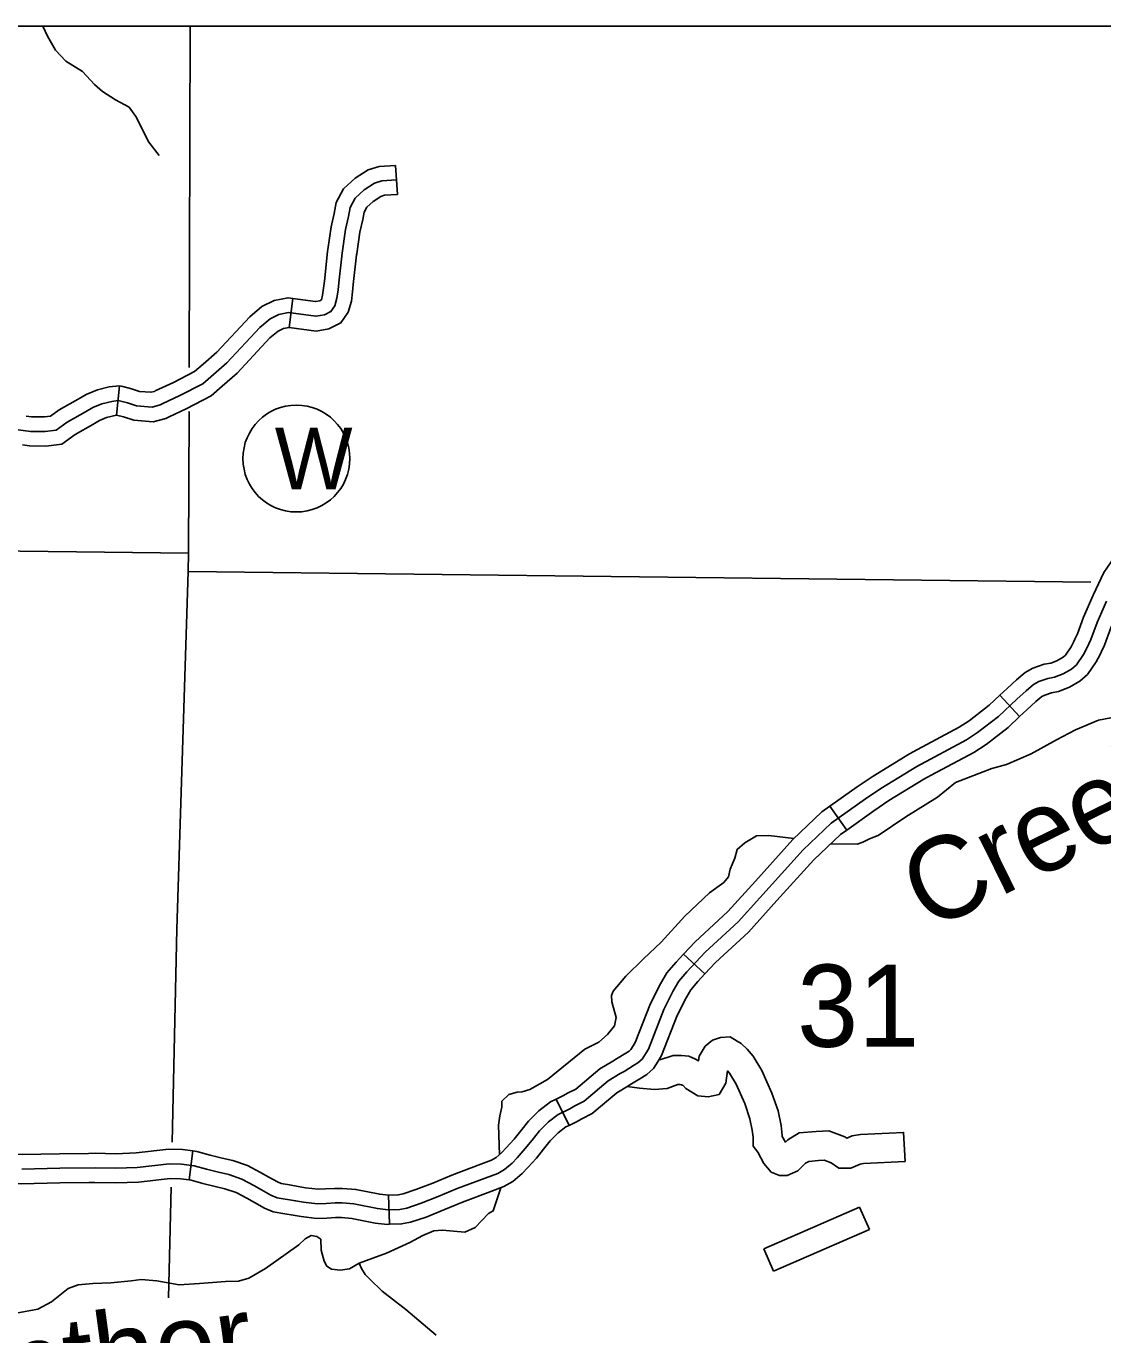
# Model space of a CAD drawing. Extents: x 0 to 3171, y 0 to 2059.
# Drawn here: x 1400.7 to 1493, y 1142.5 to 1254.6 of the extents above; entities that cross this region are included whole.
import ezdxf

# ---------------------------------------------------------------- set-up
doc = ezdxf.new("R2010")
doc.units = 0
for name, color, linetype in [('Default', 7, 'Continuous'), ('Level 35', 7, 'Continuous'), ('Level 4', 7, 'Continuous'), ('Level 45', 7, 'Continuous'), ('Level 46', 7, 'Continuous'), ('Level 5', 7, 'Continuous'), ('Level 57', 7, 'Continuous')]:
    doc.layers.add(name, color=color, linetype=linetype)

msp = doc.modelspace()

# ---------------------------------------------------------------- linework, layer by layer
at = {"layer": 'Default'}
msp.add_line((2119.81, 1254.61), (1029.42, 1254.61), dxfattribs=at)
msp.add_lwpolyline([(2119.81, 1254.61), (1029.42, 1254.61), (1029.42, 254.41), (2119.81, 254.41)], close=True, dxfattribs=at)
msp.add_lwpolyline([(2119.81, 1254.61), (1029.42, 1254.61), (1029.42, 254.41), (2119.81, 254.41)], close=True, dxfattribs=at)
msp.add_lwpolyline([(2119.81, 1254.61), (1029.42, 1254.61), (1029.42, 254.41), (2119.81, 254.41)], close=True, dxfattribs=at)
at = {"layer": 'Level 35'}
for points in [[(1402.15, 1254.61), (1402.53, 1253.76), (1403.23, 1252.57), (1404.11, 1251.62), (1405.54, 1250.72), (1406.57, 1249.62), (1407.26, 1249.02), (1408.37, 1248.31), (1409.54, 1247.67), (1410.1, 1246.88), (1411.22, 1244.68), (1412.12, 1243.52)], [(1492.61, 1195.16), (1495.78, 1195.75)], [(1469.65, 1184.55), (1471.93, 1184.53), (1472.42, 1184.7), (1472.97, 1184.98), (1473.73, 1185.28), (1476.11, 1186.86), (1478.8, 1188.57), (1480.35, 1189.8), (1483.47, 1191), (1484.71, 1191.37), (1486.85, 1192.27), (1489, 1193.46), (1490.64, 1194.32), (1492.61, 1195.16)], [(1441.29, 1157.9), (1441.19, 1160.45), (1441.3, 1161.26), (1441.47, 1161.99), (1441.48, 1162.52), (1442.07, 1163.07), (1442.78, 1163.29), (1443.21, 1163.31), (1443.89, 1163.5), (1445.39, 1164.38), (1448.58, 1166.98), (1449.79, 1167.57), (1450.53, 1168.23), (1451.12, 1168.97), (1451.28, 1169.67), (1450.9, 1171.02), (1450.86, 1171.57), (1451.02, 1171.95), (1452.11, 1173.22), (1453.63, 1174.7), (1455.13, 1176.14), (1457.17, 1178.36), (1459.27, 1180.36), (1460.1, 1180.95), (1460.51, 1181.25), (1460.89, 1181.73), (1461.05, 1182.39), (1461.43, 1183.34), (1461.65, 1184.08), (1462.31, 1184.65), (1463.31, 1185.24), (1464.35, 1185.27), (1466.5, 1185.03)], [(1429.24, 1148.62), (1431.59, 1149.48), (1433.59, 1150.41), (1434.71, 1151), (1435.65, 1151.41), (1436.4, 1151.46), (1437.33, 1151.36), (1438.32, 1151.29), (1439.19, 1151.69), (1440.33, 1152.89), (1440.72, 1153.11), (1441.38, 1155.08)], [(1399.86, 1144.34), (1401.71, 1144.69), (1402.89, 1145.33), (1404.3, 1146.45), (1405.17, 1146.78), (1406.44, 1146.9), (1407.96, 1146.95), (1409.71, 1147.13), (1410.56, 1147.22), (1411.91, 1147.11), (1413.83, 1146.78), (1415.56, 1146.9), (1417.79, 1147.06), (1418.92, 1147.08), (1419.8, 1147.34), (1421.22, 1148.17), (1424.07, 1150.19), (1424.61, 1150.71), (1425.13, 1150.99), (1425.61, 1150.92), (1425.96, 1150.68), (1425.99, 1149.74), (1426.24, 1148.79), (1426.49, 1148.37), (1426.88, 1148.12), (1427.63, 1148.02), (1428.43, 1148.15), (1429.24, 1148.62), (1429.46, 1148.17)], [(1435.86, 1142.46), (1433.26, 1144.65), (1431.22, 1146.24), (1430.16, 1147.25), (1429.76, 1147.66), (1429.46, 1148.17)]]:
    msp.add_lwpolyline(points, dxfattribs=at)
at = {"layer": 'Level 4'}
for points in [[(1414.69, 1225.38), (1414.78, 1254.61)], [(1413.22, 1159), (1413.64, 1177.24), (1414.59, 1207.88), (1414.64, 1209.46), (1414.68, 1221.6)], [(1412.91, 1145.67), (1413.13, 1155.14)]]:
    msp.add_lwpolyline(points, dxfattribs=at)
at = {"layer": 'Level 45'}
for p, q in [((1432.37, 1242.69), (1432.54, 1240.2)), ((1423.57, 1231.28), (1423.24, 1228.81)), ((1408.7, 1223.8), (1408.47, 1221.28)), ((1484.14, 1197.29), (1485.85, 1195.46)), ((1469.59, 1187.78), (1471.04, 1185.74)), ((1457.05, 1175.11), (1458.88, 1173.41)), ((1446.14, 1162.69), (1447.24, 1160.44)), ((1415.01, 1158.25), (1414.69, 1155.77)), ((1431.76, 1154.46), (1431.84, 1151.96))]:
    msp.add_line(p, q, dxfattribs=at)
for points in [[(1432.37, 1242.69), (1430.96, 1242.6), (1430.02, 1242.31), (1428.91, 1241.58), (1427.9, 1240.67), (1427.29, 1239.51), (1427.11, 1238.55), (1426.85, 1237.43), (1426.57, 1235.47)], [(1432.46, 1241.45), (1431.19, 1241.36), (1430.56, 1241.17), (1429.67, 1240.59), (1428.9, 1239.89), (1428.48, 1239.09), (1428.33, 1238.3), (1428.08, 1237.2), (1427.78, 1235.16), (1427.51, 1232.63), (1427.44, 1232.01), (1427.35, 1231.3), (1427.16, 1230.65), (1426.83, 1230.16), (1426.27, 1229.89), (1425.54, 1229.76), (1423.2, 1230.07), (1422.37, 1229.91), (1421.61, 1229.55), (1420.74, 1228.8), (1417.92, 1225.78), (1415.85, 1223.98), (1413.89, 1222.96), (1412.37, 1222.26), (1412.2, 1222.16), (1411.5, 1221.98), (1410.18, 1222.09), (1409.41, 1222.34), (1408.61, 1222.54), (1408.06, 1222.47), (1407.21, 1222.27), (1406.43, 1221.94), (1405.8, 1221.57), (1404.23, 1220.69), (1403.29, 1220), (1402.35, 1219.89), (1401.08, 1219.9), (1399.84, 1220.06)], [(1432.54, 1240.2), (1431.42, 1240.13), (1431.1, 1240.03), (1430.44, 1239.6), (1429.9, 1239.11), (1429.67, 1238.68), (1429.56, 1238.04), (1429.31, 1236.97), (1429.04, 1235.11)], [(1429.04, 1235.11), (1429.02, 1235.01), (1428.75, 1232.49), (1428.68, 1231.85), (1428.58, 1231.05), (1428.3, 1230.12), (1427.69, 1229.19), (1426.66, 1228.69), (1425.56, 1228.49), (1423.24, 1228.81)], [(1426.57, 1235.47), (1426.54, 1235.32), (1426.27, 1232.77), (1426.2, 1232.16), (1426.12, 1231.56), (1426.01, 1231.18), (1425.98, 1231.14), (1425.88, 1231.09), (1425.51, 1231.02), (1423.57, 1231.28)], [(1423.57, 1231.28), (1423.16, 1231.34), (1421.97, 1231.11), (1420.92, 1230.6), (1419.87, 1229.7), (1417.05, 1226.68), (1415.87, 1225.65)], [(1423.24, 1228.81), (1422.77, 1228.71), (1422.3, 1228.49), (1421.6, 1227.9), (1418.79, 1224.88), (1417.51, 1223.77)], [(1415.87, 1225.65), (1415.14, 1225.02), (1413.34, 1224.08), (1411.78, 1223.37), (1411.71, 1223.32), (1411.4, 1223.25), (1410.43, 1223.32), (1409.75, 1223.54), (1408.99, 1223.73)], [(1408.99, 1223.73), (1408.7, 1223.8), (1407.84, 1223.7), (1406.82, 1223.46), (1405.86, 1223.06), (1405.18, 1222.65), (1403.55, 1221.75), (1402.81, 1221.2), (1402.28, 1221.14), (1401.17, 1221.15), (1400.72, 1221.21)], [(1417.51, 1223.77), (1416.56, 1222.94), (1414.44, 1221.84), (1412.96, 1221.15), (1412.68, 1220.99), (1411.6, 1220.72), (1409.94, 1220.85), (1409.07, 1221.13), (1408.47, 1221.28)], [(1408.47, 1221.28), (1407.6, 1221.08), (1406.99, 1220.82), (1406.43, 1220.48), (1404.91, 1219.64), (1403.77, 1218.8), (1402.41, 1218.63), (1400.99, 1218.65), (1400.39, 1218.73)], [(1494.64, 1210.1), (1493.05, 1207.8), (1492.14, 1205.85), (1491.33, 1203.98), (1490.81, 1202.55), (1490.59, 1202.09)], [(1496.69, 1208.67), (1495.22, 1206.55), (1494.42, 1204.82), (1493.65, 1203.06), (1493.12, 1201.59), (1492.86, 1201.03)], [(1493.28, 1205.34), (1492.49, 1203.52), (1491.96, 1202.07), (1491.62, 1201.33), (1491.33, 1200.79), (1490.72, 1199.9), (1490.3, 1199.52), (1489.58, 1199.12), (1488.85, 1198.83), (1488.26, 1198.73), (1487.5, 1198.46), (1487.03, 1198.21), (1486.42, 1197.67), (1485.62, 1196.96), (1484.04, 1195.48), (1482.25, 1194.09), (1481.29, 1193.47), (1477.03, 1191.19), (1473.96, 1189.31)], [(1490.59, 1202.09), (1490.5, 1201.89), (1490.26, 1201.44), (1489.77, 1200.73), (1489.57, 1200.54), (1489.05, 1200.25), (1488.51, 1200.04), (1487.94, 1199.94), (1486.99, 1199.61), (1486.32, 1199.25), (1485.59, 1198.61), (1484.78, 1197.88), (1484.14, 1197.29)], [(1492.86, 1201.03), (1492.74, 1200.77), (1492.4, 1200.14), (1491.67, 1199.07), (1491.02, 1198.49), (1490.12, 1197.99), (1489.19, 1197.62), (1488.57, 1197.51), (1488, 1197.31), (1487.75, 1197.18), (1487.25, 1196.74), (1486.46, 1196.04), (1485.85, 1195.46)], [(1484.14, 1197.29), (1483.23, 1196.43), (1481.53, 1195.11), (1480.66, 1194.55), (1477.1, 1192.64)], [(1485.85, 1195.46), (1484.86, 1194.53), (1482.97, 1193.07), (1481.93, 1192.39), (1478.28, 1190.44)], [(1477.1, 1192.64), (1476.41, 1192.27), (1473.29, 1190.36), (1471.94, 1189.45), (1469.59, 1187.78)], [(1478.28, 1190.44), (1477.65, 1190.1), (1474.64, 1188.26), (1473.36, 1187.4), (1471.04, 1185.74)], [(1473.96, 1189.31), (1472.65, 1188.42), (1469.71, 1186.33), (1467.3, 1184.05), (1461.72, 1177.87), (1458.91, 1175.27), (1457.34, 1173.59), (1456.63, 1172.78), (1456.17, 1171.97), (1455.35, 1170.36), (1454.04, 1166.98), (1453.5, 1166.12), (1453.14, 1165.8), (1452.77, 1165.56), (1451.95, 1165.06), (1451.63, 1164.87), (1450.6, 1164.25), (1448.52, 1162.5), (1447.74, 1162.12), (1447.29, 1161.86), (1446.31, 1161.38), (1445.48, 1160.73), (1444.7, 1159.96), (1444.07, 1159.18), (1443.49, 1158.45), (1442.78, 1157.67), (1442.35, 1157.2), (1441.7, 1156.67), (1441.12, 1156.32), (1437.65, 1155.02), (1436.02, 1154.35), (1434.55, 1153.76), (1433.34, 1153.35), (1432.74, 1153.24), (1431.74, 1153.2), (1430.82, 1153.31), (1428.8, 1153.71), (1427.78, 1153.79), (1427.19, 1153.79), (1426.43, 1153.74), (1425.68, 1153.72), (1424.47, 1153.86), (1423.8, 1153.98), (1422.22, 1154.24), (1421.69, 1154.47), (1420.89, 1154.92), (1420.22, 1155.3), (1419.2, 1155.83), (1418.08, 1156.22), (1417.21, 1156.42), (1416.17, 1156.68), (1415.1, 1156.98), (1414.03, 1157.12), (1413, 1157.14), (1410.23, 1156.83), (1408.4, 1156.76), (1406.62, 1156.8), (1403.59, 1156.76), (1400.35, 1156.69)], [(1469.59, 1187.78), (1468.91, 1187.3), (1466.41, 1184.92), (1463.2, 1181.37)], [(1471.04, 1185.74), (1470.5, 1185.37), (1468.2, 1183.18), (1465.05, 1179.69)], [(1463.2, 1181.37), (1460.83, 1178.75), (1458.03, 1176.16), (1457.05, 1175.11)], [(1465.05, 1179.69), (1462.61, 1176.99), (1459.79, 1174.39), (1458.88, 1173.41)], [(1457.05, 1175.11), (1456.41, 1174.43), (1455.61, 1173.51), (1455.06, 1172.56), (1454.21, 1170.87), (1452.91, 1167.54), (1452.74, 1167.26)], [(1458.88, 1173.41), (1458.27, 1172.76), (1457.66, 1172.05), (1457.27, 1171.37), (1456.5, 1169.85), (1455.16, 1166.42), (1454.86, 1165.94)], [(1452.74, 1167.26), (1452.54, 1166.93), (1452.38, 1166.8), (1452.11, 1166.62), (1451.3, 1166.13), (1450.99, 1165.94), (1449.87, 1165.27), (1447.83, 1163.55), (1447.15, 1163.22), (1446.7, 1162.96), (1446.14, 1162.69)], [(1454.86, 1165.94), (1454.47, 1165.3), (1453.89, 1164.79), (1453.44, 1164.5), (1452.6, 1163.99), (1452.28, 1163.8), (1451.32, 1163.23), (1449.21, 1161.45), (1448.33, 1161.01), (1447.88, 1160.75), (1447.24, 1160.44)], [(1446.14, 1162.69), (1445.64, 1162.44), (1444.65, 1161.68), (1443.76, 1160.79), (1443.1, 1159.96), (1442.54, 1159.26), (1441.86, 1158.52), (1441.48, 1158.11), (1440.98, 1157.69), (1440.58, 1157.45), (1439.67, 1157.11)], [(1447.24, 1160.44), (1446.97, 1160.31), (1446.3, 1159.79), (1445.63, 1159.12), (1445.05, 1158.39), (1444.44, 1157.64), (1443.7, 1156.83), (1443.21, 1156.3), (1442.43, 1155.64), (1441.66, 1155.19), (1440.54, 1154.77)], [(1406.06, 1158.04), (1403.57, 1158.01), (1400.38, 1157.94), (1398.74, 1158.05), (1398.3, 1158.15), (1397.84, 1158.35)], [(1415.01, 1158.25), (1414.12, 1158.36), (1412.94, 1158.39), (1410.14, 1158.08), (1408.39, 1158.01), (1406.62, 1158.05), (1406.06, 1158.04)], [(1423.28, 1155.34), (1422.57, 1155.45), (1422.24, 1155.59), (1421.51, 1156.01), (1420.81, 1156.4), (1419.69, 1156.99), (1418.42, 1157.42), (1417.51, 1157.64), (1416.49, 1157.89), (1415.35, 1158.21), (1415.01, 1158.25)], [(1439.67, 1157.11), (1437.19, 1156.18), (1435.55, 1155.5), (1434.12, 1154.93), (1433.03, 1154.57), (1432.6, 1154.48), (1431.76, 1154.46)], [(1406.09, 1155.54), (1403.61, 1155.51), (1400.32, 1155.44), (1398.4, 1155.57), (1397.53, 1155.75), (1396.84, 1156.05)], [(1414.69, 1155.77), (1413.93, 1155.87), (1413.05, 1155.89), (1410.33, 1155.58), (1408.41, 1155.51), (1406.61, 1155.55), (1406.09, 1155.54)], [(1422.87, 1152.87), (1421.87, 1153.03), (1421.13, 1153.34), (1420.28, 1153.83), (1419.62, 1154.2), (1418.7, 1154.68), (1417.73, 1155.01), (1416.91, 1155.21), (1415.86, 1155.47), (1414.86, 1155.75), (1414.69, 1155.77)], [(1431.79, 1154.46), (1431.01, 1154.54), (1428.97, 1154.95), (1427.83, 1155.04), (1427.15, 1155.04), (1426.37, 1154.99), (1425.74, 1154.97), (1424.65, 1155.1), (1424.01, 1155.21), (1423.28, 1155.34)], [(1440.54, 1154.77), (1438.11, 1153.86), (1436.5, 1153.19), (1434.98, 1152.58), (1433.66, 1152.14), (1432.88, 1151.99), (1431.84, 1151.96)], [(1431.84, 1151.96), (1431.69, 1151.95), (1430.63, 1152.07), (1428.63, 1152.47), (1427.73, 1152.54), (1427.23, 1152.54), (1426.49, 1152.49), (1425.63, 1152.47), (1424.29, 1152.62), (1423.59, 1152.75), (1422.87, 1152.87)]]:
    msp.add_lwpolyline(points, dxfattribs=at)
at = {"layer": 'Level 46'}
for points in [[(1476.03, 1157.33), (1475.91, 1159.83), (1472.22, 1159.65), (1471.51, 1159.55), (1471.03, 1159.35), (1470.88, 1159.45), (1469.49, 1159.98), (1468.42, 1159.92), (1466.96, 1159.79), (1465.98, 1159.19), (1465.78, 1159), (1465.51, 1159.49), (1465.5, 1159.51), (1465.5, 1159.56), (1465.42, 1160.42), (1465.15, 1161.68), (1464.62, 1163.21), (1463.77, 1165.14), (1463.02, 1166.36), (1462.51, 1166.97), (1461.98, 1167.46), (1461.64, 1167.66), (1461.03, 1168.02), (1460.22, 1167.97), (1459.54, 1167.75), (1458.89, 1167.22), (1458.38, 1166.38), (1458.34, 1165.97), (1458.07, 1166.12), (1457.51, 1166.37), (1456.87, 1166.43), (1456.15, 1166.43), (1455.01, 1166.04)], [(1476.03, 1157.33), (1472.46, 1157.16), (1472.19, 1157.12), (1471.38, 1156.77), (1470.36, 1156.77), (1469.71, 1157.22), (1469.1, 1157.45), (1468.6, 1157.43), (1467.77, 1157.35), (1467.51, 1157.19), (1466.83, 1156.55), (1465.94, 1156.14), (1465.26, 1156.14), (1464.57, 1156.42), (1463.94, 1157.17), (1463.41, 1158.13), (1463, 1158.67), (1463, 1159.44), (1462.94, 1160.04), (1462.73, 1161), (1462.29, 1162.3), (1461.55, 1163.98), (1460.98, 1164.9), (1460.82, 1165.1), (1460.68, 1164.06), (1460.1, 1163.09), (1459.15, 1162.88), (1458.27, 1162.96), (1457.24, 1163.61), (1456.98, 1163.87), (1456.94, 1163.89), (1456.88, 1163.92), (1456.76, 1163.93), (1456.57, 1163.93), (1455.65, 1163.61), (1454.56, 1163.52), (1453.26, 1163.63), (1452.22, 1163.76)]]:
    msp.add_lwpolyline(points, dxfattribs=at)
at = {"layer": 'Level 5'}
for points in [[(1414.64, 1209.46), (1347.33, 1210.27)], [(1491.94, 1206.99), (1414.59, 1207.88)]]:
    msp.add_lwpolyline(points, dxfattribs=at)
at = {"layer": 'Level 57'}
for p, q in [((1472.13, 1153.44), (1463.92, 1149.86)), ((1472.97, 1151.53), (1472.13, 1153.44)), ((1464.76, 1147.95), (1472.97, 1151.53)), ((1463.92, 1149.86), (1464.76, 1147.95))]:
    msp.add_line(p, q, dxfattribs=at)
msp.add_circle((1423.87, 1217.57), 4.58, dxfattribs=at)

# ---------------------------------------------------------------- texts
at = {"layer": 'Level 35'}
for s, rotation, p in [('Creek', 26.1822, (1478.04, 1177)), ('Panther', 7.7348, (1387.82, 1134.59))]:
    msp.add_text(s, height=7.04, rotation=rotation, dxfattribs=at).set_placement(p)
at = {"layer": 'Level 5'}
msp.add_text('31', height=7.04, dxfattribs=at).set_placement((1466.78, 1167.17))
at = {"layer": 'Level 57'}
msp.add_text('W', height=5.28, dxfattribs=at).set_placement((1422.02, 1214.93))

doc.saveas('drawing.dxf')
